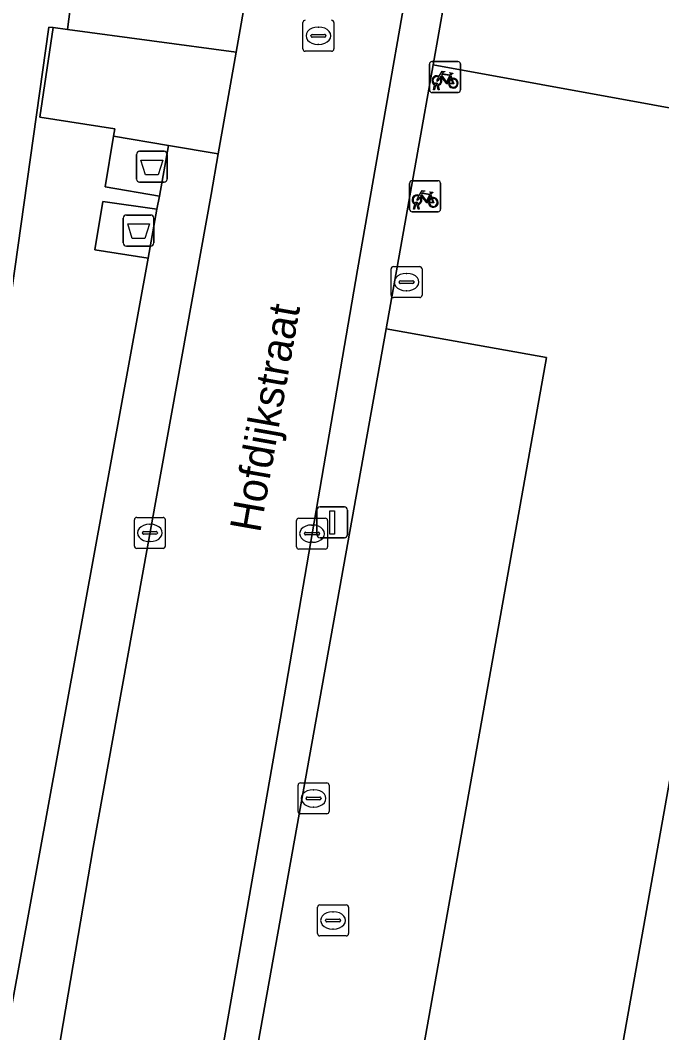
# Model space of a CAD drawing. Extents: x 161402 to 161933, y 381647 to 382315.
# Drawn here: x 161828.37 to 161849.12, y 382023.29 to 382056.02 of the extents above; entities that cross this region are included whole.
import ezdxf

# ---------------------------------------------------------------- set-up
doc = ezdxf.new("R2010")
doc.units = 0
for name, color, linetype in [('IMGEO_Afval_apart_plaats', 7, 'Continuous'), ('IMGEO_Erf', 7, 'Continuous'), ('IMGEO_Fietsenrek', 7, 'Continuous'), ('IMGEO_Groenvoorziening', 7, 'Continuous'), ('IMGEO_Kolk', 7, 'Continuous'), ('IMGEO_Lichtmast', 7, 'Continuous'), ('IMGEO_Openbare_ruimte_label', 7, 'Continuous'), ('IMGEO_Pand', 7, 'Continuous'), ('IMGEO_Parkeervlak_gesloten', 7, 'Continuous'), ('IMGEO_Rijbaan_lokaal_gesloten', 7, 'Continuous'), ('IMGEO_Rijbaan_lokaal_open', 7, 'Continuous'), ('IMGEO_Rioolput', 7, 'Continuous'), ('IMGEO_Voetpad_gesloten', 7, 'Continuous')]:
    doc.layers.add(name, color=color, linetype=linetype)

msp = doc.modelspace()

# ---------------------------------------------------------------- linework, layer by layer
at = {"layer": 'IMGEO_Afval_apart_plaats'}
for p, q in [((161832.234, 382051.78), (161833.024, 382051.78)), ((161833.024, 382051.78), (161832.234, 382051.78)), ((161832.134, 382050.88), (161832.134, 382051.68)), ((161832.134, 382051.68), (161832.134, 382050.88)), ((161833.124, 382051.68), (161833.124, 382050.88)), ((161833.124, 382050.88), (161833.124, 382051.68)), ((161833.024, 382050.78), (161832.234, 382050.78)), ((161832.234, 382050.78), (161833.024, 382050.78)), ((161831.705, 382048.818), (161831.705, 382049.618)), ((161831.705, 382049.618), (161831.705, 382048.818)), ((161831.805, 382049.718), (161832.595, 382049.718)), ((161832.595, 382049.718), (161831.805, 382049.718)), ((161832.695, 382049.618), (161832.695, 382048.818)), ((161832.695, 382048.818), (161832.695, 382049.618)), ((161832.595, 382048.718), (161831.805, 382048.718)), ((161831.805, 382048.718), (161832.595, 382048.718))]:
    msp.add_line(p, q, dxfattribs=at)
for points in [[(161832.277, 382051.494), (161832.981, 382051.494), (161832.832, 382051.024), (161832.426, 382051.024), (161832.277, 382051.494)], [(161831.848, 382049.432), (161832.552, 382049.432), (161832.403, 382048.962), (161831.997, 382048.962), (161831.848, 382049.432)]]:
    msp.add_lwpolyline(points, dxfattribs=at)
for centre, start, end in [((161832.234, 382051.68), 90, 180), ((161832.234, 382051.68), 90, 180), ((161833.024, 382051.68), 0, 90), ((161833.024, 382051.68), 360, 90), ((161832.234, 382050.88), 180, 270), ((161832.234, 382050.88), 180, 270), ((161833.024, 382050.88), 270, 0), ((161833.024, 382050.88), 270, 0), ((161831.805, 382049.618), 90, 180), ((161831.805, 382049.618), 90, 180), ((161832.595, 382049.618), 0, 90), ((161832.595, 382049.618), 360, 90), ((161831.805, 382048.818), 180, 270), ((161831.805, 382048.818), 180, 270), ((161832.595, 382048.818), 270, 0), ((161832.595, 382048.818), 270, 0)]:
    msp.add_arc(centre, 0.1, start, end, dxfattribs=at)
at = {"layer": 'IMGEO_Erf'}
msp.add_lwpolyline([(161781.596, 381964.647), (161815.795, 381959.903), (161829.294, 382055.793), (161829.439, 382055.781), (161829.897, 382055.72), (161832.064, 382072.53), (161836.652, 382071.701), (161840.585, 382094.002)], dxfattribs=at)
at = {"layer": 'IMGEO_Fietsenrek'}
for p, q in [((161841.682, 382054.681), (161842.523, 382054.681)), ((161842.523, 382054.681), (161841.682, 382054.681)), ((161841.607, 382053.756), (161841.607, 382054.597)), ((161841.607, 382054.597), (161841.607, 382053.756)), ((161842.607, 382054.606), (161842.607, 382053.765)), ((161842.607, 382053.765), (161842.607, 382054.606)), ((161842.294, 382054.23), (161842.33, 382054.135)), ((161841.734, 382053.765), (161841.773, 382053.925)), ((161841.768, 382053.765), (161841.734, 382053.765)), ((161841.803, 382053.913), (161841.768, 382053.765)), ((161841.845, 382053.937), (161841.844, 382053.941)), ((161841.886, 382053.765), (161841.852, 382053.907)), ((161841.876, 382053.948), (161841.877, 382053.941)), ((161841.884, 382053.911), (161841.919, 382053.765)), ((161841.919, 382053.765), (161841.886, 382053.765)), ((161842.532, 382053.681), (161841.691, 382053.681)), ((161841.691, 382053.681), (161842.532, 382053.681)), ((161840.962, 382049.903), (161840.962, 382050.744)), ((161840.962, 382050.744), (161840.962, 382049.903)), ((161841.037, 382050.828), (161841.878, 382050.828)), ((161841.878, 382050.828), (161841.037, 382050.828)), ((161841.962, 382050.753), (161841.962, 382049.912)), ((161841.962, 382049.912), (161841.962, 382050.753)), ((161841.2, 382050.084), (161841.199, 382050.088)), ((161841.231, 382050.095), (161841.232, 382050.088)), ((161841.649, 382050.377), (161841.685, 382050.282)), ((161841.887, 382049.828), (161841.046, 382049.828)), ((161841.046, 382049.828), (161841.887, 382049.828)), ((161841.089, 382049.912), (161841.128, 382050.072)), ((161841.123, 382049.912), (161841.089, 382049.912)), ((161841.158, 382050.06), (161841.123, 382049.912)), ((161841.241, 382049.912), (161841.207, 382050.054)), ((161841.239, 382050.058), (161841.274, 382049.912)), ((161841.274, 382049.912), (161841.241, 382049.912))]:
    msp.add_line(p, q, dxfattribs=at)
for points in [[(161841.92, 382054.207), (161842.015, 382054.371), (161842.101, 382054.357), (161842.103, 382054.348), (161842.047, 382054.337), (161842.02, 382054.292), (161842.276, 382054.251)], [(161841.941, 382054.155), (161841.889, 382054.065), (161841.849, 382054.04), (161841.85, 382054.087), (161841.905, 382054.181)], [(161842.216, 382053.963), (161842.166, 382053.963), (161841.975, 382054.214), (161841.956, 382054.182)], [(161842.263, 382054.226), (161842.006, 382054.267), (161841.989, 382054.238), (161842.156, 382054.018), (161842.263, 382054.226)], [(161842.311, 382054.128), (161842.281, 382054.205), (161842.172, 382053.987), (161842.215, 382053.987)], [(161842.245, 382053.987), (161842.365, 382053.986), (161842.321, 382054.1)], [(161842.341, 382054.107), (161842.396, 382053.962), (161842.246, 382053.962)], [(161842.276, 382054.251), (161842.301, 382054.3), (161842.295, 382054.304), (161842.272, 382054.308), (161842.26, 382054.315), (161842.259, 382054.318), (161842.261, 382054.323), (161842.356, 382054.308), (161842.358, 382054.298), (161842.348, 382054.285), (161842.336, 382054.279), (161842.322, 382054.285), (161842.294, 382054.23)], [(161841.275, 382050.354), (161841.37, 382050.518), (161841.456, 382050.504), (161841.458, 382050.495), (161841.402, 382050.484), (161841.375, 382050.439), (161841.631, 382050.398)], [(161841.618, 382050.373), (161841.361, 382050.414), (161841.344, 382050.385), (161841.511, 382050.165), (161841.618, 382050.373)], [(161841.631, 382050.398), (161841.656, 382050.447), (161841.65, 382050.451), (161841.627, 382050.455), (161841.615, 382050.462), (161841.614, 382050.465), (161841.616, 382050.47), (161841.711, 382050.455), (161841.713, 382050.445), (161841.703, 382050.432), (161841.691, 382050.426), (161841.677, 382050.432), (161841.649, 382050.377)], [(161841.296, 382050.302), (161841.244, 382050.212), (161841.204, 382050.187), (161841.205, 382050.234), (161841.26, 382050.328)], [(161841.571, 382050.11), (161841.521, 382050.11), (161841.33, 382050.361), (161841.311, 382050.329)], [(161841.666, 382050.275), (161841.636, 382050.352), (161841.527, 382050.134), (161841.57, 382050.134)], [(161841.6, 382050.134), (161841.72, 382050.133), (161841.676, 382050.247)], [(161841.696, 382050.254), (161841.751, 382050.109), (161841.601, 382050.109)]]:
    msp.add_lwpolyline(points, dxfattribs=at)
for centre, radius, start, end in [((161841.685, 382054.603), 0.0779, 92.4484, 184.2845), ((161841.685, 382054.603), 0.0779, 92.4484, 184.2845), ((161842.529, 382054.603), 0.0779, 2.4484, 94.2845), ((161842.529, 382054.603), 0.0779, 2.4484, 94.2845), ((161841.847, 382054.066), 0.159, 62.6766, 242.1369), ((161841.847, 382054.066), 0.129, 63.3192, 238.903), ((161841.847, 382054.066), 0.129, 283.6043, 43.4302), ((161841.847, 382054.066), 0.159, 283.5766, 46.6042), ((161842.374, 382053.982), 0.159, 113.3408, 178.3217), ((161842.374, 382053.982), 0.159, 187.0065, 105.7708), ((161842.374, 382053.982), 0.129, 113.923, 177.9556), ((161842.374, 382053.982), 0.129, 188.6715, 104.5883), ((161841.685, 382053.759), 0.0779, 182.4484, 274.2845), ((161841.685, 382053.759), 0.0779, 182.4484, 274.2845), ((161841.827, 382053.937), 0.0499, 12.8025, 158.6934), ((161841.847, 382054.066), 0.159, 253.9967, 271.7867), ((161841.827, 382053.937), 0.0174, 12.8025, 163.4502), ((161841.847, 382054.066), 0.129, 253.415, 269.0204), ((161842.529, 382053.759), 0.0779, 272.4484, 4.2845), ((161842.529, 382053.759), 0.0779, 272.4484, 4.2845), ((161841.04, 382050.75), 0.0779, 92.4484, 184.2845), ((161841.04, 382050.75), 0.0779, 92.4484, 184.2845), ((161841.884, 382050.75), 0.0779, 2.4484, 94.2845), ((161841.884, 382050.75), 0.0779, 2.4484, 94.2845), ((161841.202, 382050.213), 0.159, 62.6766, 242.1369), ((161841.202, 382050.213), 0.129, 63.3192, 238.903), ((161841.182, 382050.084), 0.0499, 12.8025, 158.6934), ((161841.182, 382050.084), 0.0174, 12.8025, 163.4502), ((161841.202, 382050.213), 0.129, 253.415, 269.0204), ((161841.202, 382050.213), 0.129, 283.6043, 43.4302), ((161841.202, 382050.213), 0.159, 283.5766, 46.6042), ((161841.729, 382050.129), 0.159, 113.3408, 178.3217), ((161841.729, 382050.129), 0.159, 187.0065, 105.7708), ((161841.729, 382050.129), 0.129, 113.923, 177.9556), ((161841.729, 382050.129), 0.129, 188.6715, 104.5883), ((161841.04, 382049.906), 0.0779, 182.4484, 274.2845), ((161841.04, 382049.906), 0.0779, 182.4484, 274.2845), ((161841.202, 382050.213), 0.159, 253.9967, 271.7867), ((161841.884, 382049.906), 0.0779, 272.4484, 4.2845), ((161841.884, 382049.906), 0.0779, 272.4484, 4.2845)]:
    msp.add_arc(centre, radius, start, end, dxfattribs=at)
at = {"layer": 'IMGEO_Groenvoorziening'}
msp.add_lwpolyline([(161832.505, 382048.322), (161830.782, 382048.597), (161831.04, 382050.152), (161832.794, 382049.905), (161832.872, 382050.33), (161831.118, 382050.626), (161831.391, 382052.269), (161831.43, 382052.504), (161829.006, 382052.887), (161829.439, 382055.781), (161829.294, 382055.793), (161815.795, 381959.903), (161816.367, 381959.82), (161816.701, 381961.668), (161822.827, 381995.34)], close=True, dxfattribs=at)
at = {"layer": 'IMGEO_Kolk'}
for p, q in [((161840.363, 382047.126), (161840.363, 382047.978)), ((161840.438, 382048.052), (161841.29, 382048.052)), ((161840.851, 382047.832), (161840.876, 382047.832)), ((161841.364, 382047.978), (161841.364, 382047.126)), ((161840.622, 382047.546), (161840.622, 382047.558)), ((161841.06, 382047.509), (161840.662, 382047.509)), ((161840.665, 382047.595), (161841.063, 382047.595)), ((161841.106, 382047.558), (161841.106, 382047.546)), ((161840.874, 382047.272), (161840.849, 382047.272)), ((161841.29, 382047.052), (161840.438, 382047.052)), ((161832.139, 382039.944), (161832.991, 382039.944)), ((161832.064, 382039.018), (161832.064, 382039.87)), ((161832.552, 382039.724), (161832.577, 382039.724)), ((161833.065, 382039.87), (161833.065, 382039.018)), ((161837.308, 382038.993), (161837.308, 382039.845)), ((161837.383, 382039.919), (161838.235, 382039.919)), ((161837.796, 382039.699), (161837.821, 382039.699)), ((161838.309, 382039.845), (161838.309, 382038.993)), ((161832.323, 382039.438), (161832.323, 382039.45)), ((161832.761, 382039.401), (161832.363, 382039.401)), ((161832.366, 382039.487), (161832.764, 382039.487)), ((161832.807, 382039.45), (161832.807, 382039.438)), ((161837.567, 382039.413), (161837.567, 382039.425)), ((161838.005, 382039.376), (161837.607, 382039.376)), ((161837.61, 382039.462), (161838.008, 382039.462)), ((161838.051, 382039.425), (161838.051, 382039.413)), ((161832.575, 382039.164), (161832.55, 382039.164)), ((161837.819, 382039.139), (161837.794, 382039.139)), ((161832.991, 382038.944), (161832.139, 382038.944)), ((161838.235, 382038.919), (161837.383, 382038.919)), ((161837.357, 382030.436), (161837.357, 382031.288)), ((161837.432, 382031.362), (161838.284, 382031.362)), ((161837.845, 382031.142), (161837.87, 382031.142)), ((161838.358, 382031.288), (161838.358, 382030.436)), ((161837.616, 382030.856), (161837.616, 382030.868)), ((161838.054, 382030.819), (161837.656, 382030.819)), ((161837.659, 382030.905), (161838.057, 382030.905)), ((161838.1, 382030.868), (161838.1, 382030.856)), ((161837.868, 382030.582), (161837.843, 382030.582)), ((161838.284, 382030.362), (161837.432, 382030.362))]:
    msp.add_line(p, q, dxfattribs=at)
for points in [[(161840.363, 382047.126), (161840.363, 382047.978)], [(161840.438, 382048.052), (161841.29, 382048.052)], [(161841.364, 382047.978), (161841.364, 382047.126)], [(161841.29, 382047.052), (161840.438, 382047.052)], [(161832.139, 382039.944), (161832.991, 382039.944)], [(161832.064, 382039.018), (161832.064, 382039.87)], [(161833.065, 382039.87), (161833.065, 382039.018)], [(161837.308, 382038.993), (161837.308, 382039.845)], [(161837.383, 382039.919), (161838.235, 382039.919)], [(161838.309, 382039.845), (161838.309, 382038.993)], [(161832.991, 382038.944), (161832.139, 382038.944)], [(161838.235, 382038.919), (161837.383, 382038.919)], [(161837.357, 382030.436), (161837.357, 382031.288)], [(161837.432, 382031.362), (161838.284, 382031.362)], [(161838.358, 382031.288), (161838.358, 382030.436)], [(161838.284, 382030.362), (161837.432, 382030.362)]]:
    msp.add_lwpolyline(points, dxfattribs=at)
for centre, radius, start, end in [((161840.44, 382047.976), 0.0765, 91.552, 178.448), ((161840.44, 382047.976), 0.0765, 91.552, 178.448), ((161841.288, 382047.976), 0.0765, 1.552, 88.448), ((161841.288, 382047.976), 0.0765, 1.552, 88.448), ((161840.662, 382047.555), 0.0403, 85.8775, 175.7526), ((161840.659, 382047.545), 0.0366, 178.938, 274.7102), ((161841.063, 382047.552), 0.043, 264.8664, 352.4533), ((161841.067, 382047.557), 0.0386, 1.7309, 96.639), ((161840.44, 382047.128), 0.0765, 181.552, 268.448), ((161840.44, 382047.128), 0.0765, 181.552, 268.448), ((161841.288, 382047.128), 0.0765, 271.552, 358.448), ((161841.288, 382047.128), 0.0765, 271.552, 358.448), ((161832.141, 382039.868), 0.0765, 91.552, 178.448), ((161832.141, 382039.868), 0.0765, 91.552, 178.448), ((161832.989, 382039.868), 0.0765, 1.552, 88.448), ((161832.989, 382039.868), 0.0765, 1.552, 88.448), ((161837.385, 382039.843), 0.0765, 91.552, 178.448), ((161837.385, 382039.843), 0.0765, 91.552, 178.448), ((161838.233, 382039.843), 0.0765, 1.552, 88.448), ((161838.233, 382039.843), 0.0765, 1.552, 88.448), ((161832.363, 382039.447), 0.0403, 85.8775, 175.7526), ((161832.36, 382039.437), 0.0366, 178.938, 274.7102), ((161832.764, 382039.444), 0.043, 264.8664, 352.4533), ((161832.768, 382039.449), 0.0386, 1.7309, 96.639), ((161837.607, 382039.422), 0.0403, 85.8775, 175.7526), ((161837.604, 382039.412), 0.0366, 178.938, 274.7102), ((161838.008, 382039.419), 0.043, 264.8664, 352.4533), ((161838.012, 382039.424), 0.0386, 1.7309, 96.639), ((161832.141, 382039.02), 0.0765, 181.552, 268.448), ((161832.141, 382039.02), 0.0765, 181.552, 268.448), ((161832.989, 382039.02), 0.0765, 271.552, 358.448), ((161832.989, 382039.02), 0.0765, 271.552, 358.448), ((161837.385, 382038.995), 0.0765, 181.552, 268.448), ((161837.385, 382038.995), 0.0765, 181.552, 268.448), ((161838.233, 382038.995), 0.0765, 271.552, 358.448), ((161838.233, 382038.995), 0.0765, 271.552, 358.448), ((161837.434, 382031.286), 0.0765, 91.552, 178.448), ((161837.434, 382031.286), 0.0765, 91.552, 178.448), ((161838.282, 382031.286), 0.0765, 1.552, 88.448), ((161838.282, 382031.286), 0.0765, 1.552, 88.448), ((161837.656, 382030.865), 0.0403, 85.8775, 175.7526), ((161837.653, 382030.855), 0.0366, 178.938, 274.7102), ((161838.057, 382030.862), 0.043, 264.8664, 352.4533), ((161838.061, 382030.867), 0.0386, 1.7309, 96.639), ((161837.434, 382030.438), 0.0765, 181.552, 268.448), ((161837.434, 382030.438), 0.0765, 181.552, 268.448), ((161838.282, 382030.438), 0.0765, 271.552, 358.448), ((161838.282, 382030.438), 0.0765, 271.552, 358.448)]:
    msp.add_arc(centre, radius, start, end, dxfattribs=at)
for centre, major_axis, ratio, start_param, end_param in [((161840.85, 382047.552), (-0.387, 0.002), 0.722429, 4.712389, 7.853982), ((161840.875, 382047.552), (-0.39, 0.002), 0.717154, 1.570796, 4.712389), ((161832.551, 382039.444), (-0.387, 0.002), 0.722429, 4.712389, 7.853982), ((161832.576, 382039.444), (-0.39, 0.002), 0.717154, 1.570796, 4.712389), ((161837.795, 382039.419), (-0.387, 0.002), 0.722429, 4.712389, 7.853982), ((161837.82, 382039.419), (-0.39, 0.002), 0.717154, 1.570796, 4.712389), ((161837.844, 382030.862), (-0.387, 0.002), 0.722429, 4.712389, 7.853982), ((161837.869, 382030.862), (-0.39, 0.002), 0.717154, 1.570796, 4.712389)]:
    msp.add_ellipse(centre, major_axis=major_axis, ratio=ratio, start_param=start_param, end_param=end_param, dxfattribs=at)
at = {"layer": 'IMGEO_Lichtmast'}
for p, q in [((161838.066, 382040.283), (161838.856, 382040.283)), ((161838.856, 382040.283), (161838.066, 382040.283)), ((161837.966, 382039.383), (161837.966, 382040.183)), ((161837.966, 382040.183), (161837.966, 382039.383)), ((161838.956, 382040.183), (161838.956, 382039.383)), ((161838.956, 382039.383), (161838.956, 382040.183)), ((161838.856, 382039.283), (161838.066, 382039.283)), ((161838.066, 382039.283), (161838.856, 382039.283))]:
    msp.add_line(p, q, dxfattribs=at)
msp.add_lwpolyline([(161838.386, 382040.158), (161838.536, 382040.158), (161838.536, 382039.408), (161838.386, 382039.408), (161838.386, 382040.158)], dxfattribs=at)
for centre, start, end in [((161838.066, 382040.183), 90, 180), ((161838.066, 382040.183), 90, 180), ((161838.856, 382040.183), 0, 90), ((161838.856, 382040.183), 360, 90), ((161838.066, 382039.383), 180, 270), ((161838.066, 382039.383), 180, 270), ((161838.856, 382039.383), 270, 0), ((161838.856, 382039.383), 270, 0)]:
    msp.add_arc(centre, 0.1, start, end, dxfattribs=at)
at = {"layer": 'IMGEO_Pand'}
msp.add_lwpolyline([(161881.604, 382083.709), (161864.747, 382086.071), (161864.705, 382087.108), (161857.022, 382088.5), (161857.282, 382089.936), (161856.514, 382090.075), (161856.605, 382090.577), (161849.637, 382091.837), (161848.409, 382092.059), (161845.824, 382077.508), (161842.463, 382058.722), (161841.73, 382054.571), (161852.314, 382052.645), (161867.831, 382049.852), (161874.803, 382048.597), (161875.966, 382054.535), (161876.056, 382054.517), (161876.327, 382055.897), (161879.777, 382073.754), (161879.674, 382073.772), (161879.866, 382074.825), (161879.984, 382074.802), (161880.941, 382079.709), (161880.846, 382079.728)], close=True, dxfattribs=at)
at = {"layer": 'IMGEO_Parkeervlak_gesloten'}
for points in [[(161836.914, 382063.862), (161838.217, 382071.422), (161836.652, 382071.701), (161832.064, 382072.53), (161829.897, 382055.72), (161835.352, 382054.98)], [(161851.778, 382044.94), (161842.359, 381992.125), (161852.522, 381990.313), (161861.941, 382043.127)]]:
    msp.add_lwpolyline(points, close=True, dxfattribs=at)
for points in [[(161840.202, 382046.042), (161831.954, 382000), (161830.987, 381994.574), (161834.474, 381994.007)], [(161836.518, 381995.382), (161845.388, 382045.117), (161840.202, 382046.042)]]:
    msp.add_lwpolyline(points, dxfattribs=at)
at = {"layer": 'IMGEO_Rijbaan_lokaal_gesloten'}
msp.add_lwpolyline([(161864.341, 382023.003), (161863.082, 382023.239), (161863.131, 382023.567), (161862.931, 382023.789), (161863.275, 382024.22), (161867.831, 382049.852), (161852.314, 382052.645), (161841.73, 382054.571), (161840.202, 382046.042), (161845.388, 382045.117), (161836.518, 381995.382)], dxfattribs=at)
msp.add_lwpolyline([(161851.778, 382044.94), (161861.941, 382043.127), (161852.522, 381990.313), (161842.359, 381992.125)], close=True, dxfattribs=at)
at = {"layer": 'IMGEO_Rijbaan_lokaal_open'}
for points in [[(161840.202, 382046.042), (161841.73, 382054.571), (161842.463, 382058.722), (161845.824, 382077.508), (161848.409, 382092.059), (161849.637, 382091.837), (161850.155, 382094.961), (161849.74, 382095.198), (161861.265, 382106.705), (161864.069, 382106.453), (161863.229, 382133.182), (161861.825, 382133.473), (161862.193, 382125.995), (161862.49, 382119.308), (161862.638, 382116.087)], [(161859.869, 382107.508), (161855.583, 382102.928), (161847.522, 382094.137), (161844.797, 382079.199), (161841.729, 382061.924), (161839.275, 382047.946), (161836.784, 382033.46), (161833.899, 382016.966), (161830.695, 382000), (161827.554, 381983.498), (161825.196, 381970.616), (161825.164, 381970.44), (161822.54, 381956.991), (161822.45, 381956.505), (161823.681, 381955.575), (161824.173, 381957.682), (161825.719, 381965.932), (161826.684, 381971.203), (161827.883, 381977.756), (161828.609, 381981.506), (161828.968, 381983.243), (161830.987, 381994.574), (161831.954, 382000), (161840.202, 382046.042)], [(161839.275, 382047.946), (161841.729, 382061.924), (161844.797, 382079.199), (161847.522, 382094.137), (161855.583, 382102.928), (161859.869, 382107.508)], [(161840.146, 382082.597), (161838.823, 382074.942), (161838.217, 382071.422), (161836.914, 382063.862), (161835.352, 382054.98), (161834.774, 382051.699), (161834.543, 382050.384), (161830.73, 382029.273), (161829.195, 382020.232)], [(161833.899, 382016.966), (161836.784, 382033.46), (161839.275, 382047.946)]]:
    msp.add_lwpolyline(points, dxfattribs=at)
for points in [[(161835.352, 382054.98), (161829.897, 382055.72), (161829.439, 382055.781), (161829.006, 382052.887), (161831.43, 382052.504), (161831.391, 382052.269), (161833.171, 382051.969), (161834.774, 382051.699)], [(161827.39, 382010.57), (161829.195, 382020.232), (161830.73, 382029.273), (161834.543, 382050.384), (161834.774, 382051.699), (161833.171, 382051.969), (161832.872, 382050.33), (161832.794, 382049.905), (161832.505, 382048.322), (161822.827, 381995.34), (161816.701, 381961.668), (161816.367, 381959.82), (161815.783, 381956.589), (161816.977, 381956.412), (161817.094, 381956.896), (161817.254, 381957.834), (161824.386, 381993.913), (161825.157, 381998.089), (161825.499, 382000)]]:
    msp.add_lwpolyline(points, close=True, dxfattribs=at)
at = {"layer": 'IMGEO_Rioolput'}
for p, q in [((161837.514, 382055.09), (161837.514, 382055.942)), ((161838.002, 382055.796), (161838.027, 382055.796)), ((161838.515, 382055.942), (161838.515, 382055.09)), ((161837.773, 382055.51), (161837.773, 382055.522)), ((161838.211, 382055.473), (161837.813, 382055.473)), ((161837.816, 382055.559), (161838.214, 382055.559)), ((161838.257, 382055.522), (161838.257, 382055.51)), ((161838.441, 382055.016), (161837.589, 382055.016)), ((161838.025, 382055.236), (161838, 382055.236)), ((161837.987, 382026.491), (161837.987, 382027.343)), ((161838.062, 382027.417), (161838.914, 382027.417)), ((161838.475, 382027.197), (161838.5, 382027.197)), ((161838.988, 382027.343), (161838.988, 382026.491)), ((161838.246, 382026.911), (161838.246, 382026.923)), ((161838.684, 382026.874), (161838.286, 382026.874)), ((161838.289, 382026.96), (161838.687, 382026.96)), ((161838.73, 382026.923), (161838.73, 382026.911)), ((161838.498, 382026.637), (161838.473, 382026.637)), ((161838.914, 382026.417), (161838.062, 382026.417))]:
    msp.add_line(p, q, dxfattribs=at)
for points in [[(161837.514, 382055.09), (161837.514, 382055.942)], [(161838.515, 382055.942), (161838.515, 382055.09)], [(161838.441, 382055.016), (161837.589, 382055.016)], [(161837.987, 382026.491), (161837.987, 382027.343)], [(161838.062, 382027.417), (161838.914, 382027.417)], [(161838.988, 382027.343), (161838.988, 382026.491)], [(161838.914, 382026.417), (161838.062, 382026.417)]]:
    msp.add_lwpolyline(points, dxfattribs=at)
for centre, radius, start, end in [((161837.591, 382055.94), 0.0765, 91.552, 178.448), ((161837.591, 382055.94), 0.0765, 91.552, 178.448), ((161838.439, 382055.94), 0.0765, 1.552, 88.448), ((161838.439, 382055.94), 0.0765, 1.552, 88.448), ((161837.813, 382055.519), 0.0403, 85.8775, 175.7526), ((161837.81, 382055.509), 0.0366, 178.938, 274.7102), ((161838.214, 382055.516), 0.043, 264.8664, 352.4533), ((161838.218, 382055.521), 0.0386, 1.7309, 96.639), ((161837.591, 382055.092), 0.0765, 181.552, 268.448), ((161837.591, 382055.092), 0.0765, 181.552, 268.448), ((161838.439, 382055.092), 0.0765, 271.552, 358.448), ((161838.439, 382055.092), 0.0765, 271.552, 358.448), ((161838.064, 382027.341), 0.0765, 91.552, 178.448), ((161838.064, 382027.341), 0.0765, 91.552, 178.448), ((161838.912, 382027.341), 0.0765, 1.552, 88.448), ((161838.912, 382027.341), 0.0765, 1.552, 88.448), ((161838.286, 382026.92), 0.0403, 85.8775, 175.7526), ((161838.283, 382026.91), 0.0366, 178.938, 274.7102), ((161838.687, 382026.917), 0.043, 264.8664, 352.4533), ((161838.691, 382026.922), 0.0386, 1.7309, 96.639), ((161838.064, 382026.493), 0.0765, 181.552, 268.448), ((161838.064, 382026.493), 0.0765, 181.552, 268.448), ((161838.912, 382026.493), 0.0765, 271.552, 358.448), ((161838.912, 382026.493), 0.0765, 271.552, 358.448)]:
    msp.add_arc(centre, radius, start, end, dxfattribs=at)
for centre, major_axis, ratio, start_param, end_param in [((161838.001, 382055.516), (-0.387, 0.002), 0.722429, 4.712389, 7.853982), ((161838.026, 382055.516), (-0.39, 0.002), 0.717154, 1.570796, 4.712389), ((161838.474, 382026.917), (-0.387, 0.002), 0.722429, 4.712389, 7.853982), ((161838.499, 382026.917), (-0.39, 0.002), 0.717154, 1.570796, 4.712389)]:
    msp.add_ellipse(centre, major_axis=major_axis, ratio=ratio, start_param=start_param, end_param=end_param, dxfattribs=at)
at = {"layer": 'IMGEO_Voetpad_gesloten'}
for points in [[(161833.171, 382051.969), (161831.391, 382052.269), (161831.118, 382050.626), (161832.872, 382050.33)], [(161832.794, 382049.905), (161831.04, 382050.152), (161830.782, 382048.597), (161832.505, 382048.322)]]:
    msp.add_lwpolyline(points, close=True, dxfattribs=at)

# ---------------------------------------------------------------- texts
at = {"layer": 'IMGEO_Openbare_ruimte_label'}
msp.add_text('Hofdijkstraat', height=1, rotation=79.9821, dxfattribs=at).set_placement((161836.13, 382039.423))

doc.saveas('drawing.dxf')
